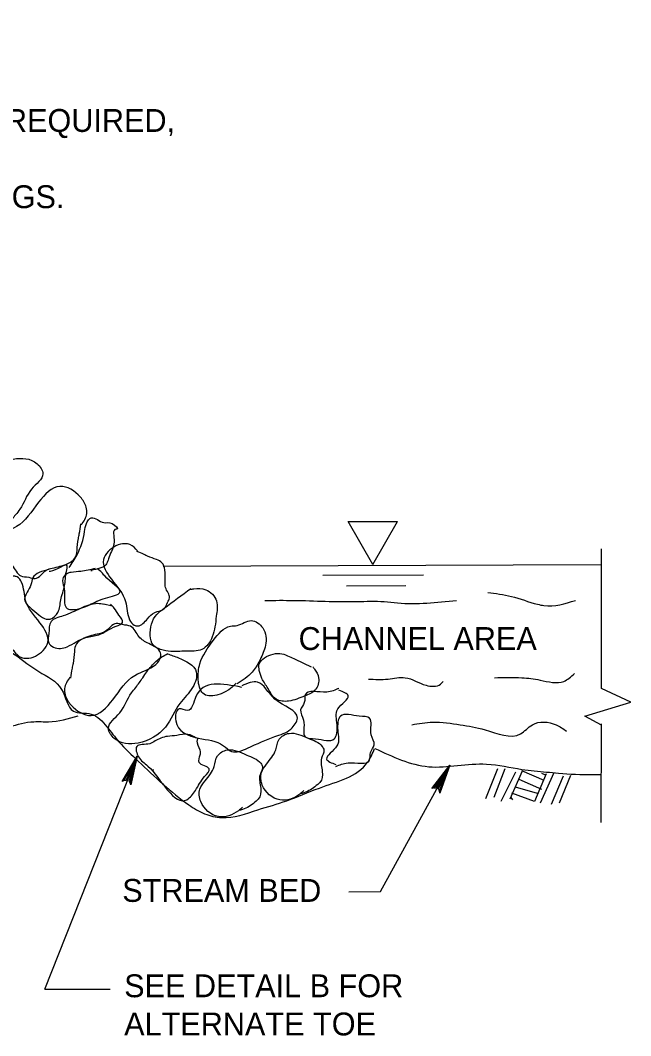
# Model space of a CAD drawing. Extents: x 5 to 910, y -47 to 547.
# Drawn here: x 524.8 to 598, y 110.4 to 232.2 of the extents above; entities that cross this region are included whole.
import ezdxf

# ---------------------------------------------------------------- set-up
doc = ezdxf.new("R2010")
doc.units = 0
for name, color, linetype in [('1', 7, 'Continuous'), ('2', 7, 'Continuous'), ('3', 7, 'Continuous')]:
    doc.layers.add(name, color=color, linetype=linetype)

msp = doc.modelspace()

# ---------------------------------------------------------------- linework, layer by layer
at = {"layer": '1'}
for p, q in [((582, 142.38), (580.54, 138.76)), ((582.85, 142.36), (581.55, 138.92)), ((584.13, 141.99), (582.39, 138.44)), ((584.93, 142.1), (583.47, 138.72)), ((587.59, 140.96), (584.89, 142.13)), ((587.81, 141.76), (586.44, 138.47)), ((588.73, 141.88), (587.1, 138.26)), ((587.77, 141.62), (587.31, 141.81)), ((589.87, 141.51), (588.41, 138.08)), ((590.74, 141.58), (589.39, 138.24)), ((586.78, 139.4), (584.13, 140.16)), ((587.29, 139.88), (584.59, 141.1)), ((583.81, 138.65), (583.63, 138.95)), ((586.44, 138.47), (583.72, 139.47))]:
    msp.add_line(p, q, dxfattribs=at)
at = {"layer": '2'}
for p, q in [((564.09, 172.03), (570.01, 172.03)), ((567.04, 166.88), (564.09, 172.03)), ((567.04, 166.88), (570.01, 172.03)), ((594.47, 152.03), (594.47, 168.76)), ((541.92, 166.7), (594.38, 166.9)), ((561.05, 165.6), (573.13, 165.65)), ((563.88, 164.32), (570.98, 164.37)), ((594.43, 135.93), (594.45, 147.76)), ((527.73, 115.95), (538.81, 143.91)), ((567.98, 127.67), (576.28, 142.81)), ((564.18, 127.62), (567.98, 127.67)), ((527.73, 115.95), (535.54, 115.95))]:
    msp.add_line(p, q, dxfattribs=at)
for points in [[(594.47, 147.62), (592.46, 148.69), (597.95, 150.39), (594.47, 152.03)], [(537.21, 140.98), (537.46, 141.01), (538.81, 143.91), (537.21, 140.98), (537, 140.87), (538.81, 143.91), (537.78, 140.89), (537.96, 140.69), (538.81, 143.91), (538.03, 140.46), (537.96, 140.69)], [(574.32, 140.09), (574.59, 140.09), (576.28, 142.81), (574.32, 140.09), (574.11, 140.02), (576.28, 142.81), (574.89, 139.93), (575.05, 139.72), (576.28, 142.81), (575.09, 139.47), (575.05, 139.72)]]:
    msp.add_lwpolyline(points, dxfattribs=at)
for points in [[(580.81, 163.54), (583.65, 163.06), (586.78, 162.12), (587.56, 161.96), (591.34, 162.58)], [(554.11, 162.58), (557.57, 162.58), (565.12, 162.44), (568.41, 162.44), (569.99, 162.28), (577.06, 162.58)], [(581.61, 153.31), (584.91, 153.31), (587.1, 153.02), (589.94, 152.86), (591.2, 153.8)], [(566.51, 153.15), (568.87, 153.15), (570.93, 153.31), (573.42, 152.4), (575.16, 152.54), (575.48, 152.86)], [(503.41, 144.9), (508.88, 143.93), (512.06, 145.01), (517.53, 145.88), (520.55, 146.43), (526.41, 148.03), (528.17, 148.03), (531.72, 148.72)], [(571.71, 147.66), (574.22, 147.98), (577.52, 147.66), (580.49, 147.05), (584.75, 146.57), (586.17, 147.66), (589, 147.66), (590.26, 146.89)], [(567.29, 144.83), (573.74, 142.63), (580.68, 142.95), (584.91, 142.31), (587.88, 141.99), (589.3, 141.85), (593.37, 141.69), (594.33, 141.69)]]:
    msp.add_spline(points, degree=3, dxfattribs=at)
at = {"layer": '3'}
for p, q in [((534.78, 162.17), (535.79, 161.92)), ((557.75, 155.53), (559.63, 154.6)), ((540.71, 142.29), (540.68, 142.08))]:
    msp.add_line(p, q, dxfattribs=at)
for points in [[(455.6, 232.18), (447.66, 230.07), (438.55, 227.81), (435.12, 226.62), (434.05, 223.3), (435.12, 222.13), (440.2, 217.4), (445.42, 213.35), (450.86, 208.86), (456.67, 204.95), (462.35, 201.15), (469.35, 196.3), (476.67, 190.15), (481.77, 185.67), (486.39, 181.98), (489.82, 180.11), (491.36, 179.49), (493.97, 176.19), (495.86, 174.75), (498.93, 174.39), (499.05, 172.99), (499.64, 172.62), (500.72, 172.62), (502.61, 170.86), (505.93, 168.37), (508.88, 166.01), (509.25, 165.05), (510.9, 164.57), (514.1, 162.33), (516.23, 160.54), (520.48, 158.19), (524.17, 156.04), (527, 154.05), (529.73, 151.9), (531.14, 149.31), (533.27, 148.94), (535.17, 147.41), (536.59, 145.63), (538.95, 143.27), (544.99, 138.05), (546.88, 136.98), (548.9, 136.52), (553.27, 137.46), (556.72, 138.54), (560.63, 140.07), (566.42, 143.16), (567.25, 144.8)], [(520.44, 168.83), (519.09, 169.33), (516.96, 171), (517.39, 172.88), (518.95, 174.8), (520.67, 177.63), (523.94, 179.53), (526.8, 178.98), (527.48, 177.77), (526.13, 175.94), (524.74, 173.52), (524.21, 172.85), (523.39, 171.71), (522.36, 170.29), (521.12, 169.24), (520.39, 168.83)], [(532.1, 171.66), (532.75, 172.99), (532.68, 173.77), (531.99, 174.98), (529.54, 176.26), (526.98, 174.36), (524.33, 171.43), (521.81, 170.13), (521.24, 169.26), (521.26, 168.73), (522.68, 167.61), (523.82, 166.77), (524.83, 165.53), (525.79, 165.35), (526.55, 165.21), (527.89, 166.2), (528.6, 166.45), (530.46, 167), (531.33, 167.66), (531.58, 168.57), (531.74, 169.99), (531.85, 170.57), (532.04, 171.75)], [(530.64, 166.52), (531.58, 168.03), (532.49, 170.86), (532.7, 171.8), (533.29, 172.49), (534.78, 171.91), (535.81, 171.8), (536.38, 171.11), (536.27, 171.11), (536.04, 169.63), (535.7, 168.46), (535.35, 167.57), (534.55, 166.52), (533.29, 166.17), (533.41, 166.17)], [(538.85, 168.51), (537.92, 169.28), (537.32, 169.38), (536.25, 169.12), (534.76, 167.48), (535.7, 165.12), (537.41, 162.44), (537.89, 160.25), (538.44, 159.61), (538.85, 159.51), (540.02, 160.38), (540.89, 161.12), (542.08, 161.64), (542.42, 162.33), (542.67, 162.88), (542.19, 164.14), (542.15, 164.73), (542.1, 166.26), (541.76, 167.09), (541.12, 167.48), (540.04, 167.87), (539.61, 168.09), (538.76, 168.46)], [(528.24, 166.29), (526.29, 165.28), (526.06, 164.46), (525.29, 162.74), (526.52, 161.25), (528.35, 160.34), (529.29, 161.14), (529.63, 162.63), (530.09, 164.34), (530.3, 166.06), (530.41, 166.74), (528.35, 166.06), (528.24, 166.06)], [(533.75, 166.4), (532.04, 166.06), (530.89, 165.94), (530.3, 165.74), (529.86, 165.17), (529.98, 164.23), (530.09, 163.2), (530.41, 161.6), (531.12, 161.48), (533.07, 162.05), (535.01, 162.86), (536.73, 163.54), (534.9, 165.51), (534.55, 165.94), (533.98, 166.4)], [(524.01, 156.49), (524.92, 155.72), (525.52, 155.63), (526.59, 155.9), (528.08, 157.52), (527.14, 159.9), (525.42, 162.56), (524.94, 164.75), (524.39, 165.39), (524.01, 165.49), (522.84, 164.64), (521.95, 163.91), (520.78, 163.38), (520.44, 162.69), (520.16, 162.15), (520.64, 160.89), (520.69, 160.29), (520.73, 158.74), (521.08, 157.91), (521.72, 157.52), (522.79, 157.16), (523.23, 156.93), (524.1, 156.54)], [(545.15, 163.91), (545.58, 163.98), (547.02, 163.86), (548.3, 162.51), (548.28, 160.68), (547.8, 158.21), (546.56, 156.7), (544.6, 156.49), (542.83, 156.45), (541.6, 156.7), (540.73, 157.2), (540.36, 158.35), (541.14, 160.89), (542.03, 161.64), (545.24, 164.02)], [(534.85, 162.1), (534.05, 162.19), (531.99, 161.62), (529.93, 160.73), (528.47, 160.04), (528.19, 158.62), (528.19, 157.48), (529.59, 156.82), (530.39, 157.02), (532.63, 158.12), (534.19, 158.46), (536.27, 159.49), (537.05, 159.93), (536.61, 160.8), (536.04, 161.64), (535.61, 162.12)], [(530.73, 153.36), (530.09, 152.01), (530.16, 151.26), (530.85, 150.04), (533.29, 148.76), (535.86, 150.66), (538.51, 153.59), (541.03, 154.89), (541.6, 155.76), (541.6, 156.27), (540.18, 157.39), (539.01, 158.23), (538.01, 159.47), (537.05, 159.67), (536.29, 159.81), (534.94, 158.83), (534.23, 158.58), (532.38, 158.03), (531.51, 157.36), (531.26, 156.43), (531.1, 155.03), (530.98, 154.44), (530.8, 153.27)], [(550.64, 152.67), (550.16, 152.17), (546.66, 151.44), (546.11, 153.06), (546.31, 154.98), (547.94, 157.8), (549.97, 159.49), (550.77, 159.58), (552.47, 160.16), (553.84, 159.29), (554.18, 157.2), (553.52, 155.47), (553.45, 155.33), (552.58, 153.98), (550.77, 152.58)], [(542.42, 156.17), (543.75, 155.69), (545.88, 154), (545.44, 152.15), (543.91, 150.23), (542.19, 147.39), (538.9, 145.47), (536.04, 146.02), (535.35, 147.23), (536.7, 149.08), (538.1, 151.48), (538.63, 152.15), (539.45, 153.31), (540.5, 154.71), (541.74, 155.79), (542.45, 156.2)], [(559.83, 154.62), (560.06, 154.34), (560.54, 153.29), (560.15, 151.85), (558.87, 151.12), (556.95, 150.5), (555.44, 150.73), (554.48, 152.01), (553.75, 153.22), (553.43, 154.18), (553.43, 154.96), (554.07, 155.69), (556.15, 156.17), (557.02, 155.85), (557.75, 155.53)], [(551.32, 152.15), (545.83, 151.07), (544.83, 149.36), (543.82, 149.56), (543.41, 148.14), (546.11, 146.06), (549.13, 145.15), (550.11, 144.46), (552.01, 144.85), (555.3, 146.25), (557.2, 147.14), (558, 148.46), (555.3, 150.75), (553.22, 152.77), (551.32, 152.35)], [(562.97, 152.03), (561.53, 151.58), (558.94, 151.26), (558.83, 150.34), (558.39, 149.45), (558.74, 148.21), (558.94, 146.2), (560.18, 145.97), (562.42, 145.97), (562.76, 147.66), (562.85, 149.56), (564.09, 151.14), (562.97, 151.8)], [(562.62, 142.65), (564.07, 143.09), (566.65, 143.43), (566.77, 144.35), (567.2, 145.24), (566.86, 146.45), (566.65, 148.46), (565.42, 148.69), (563.17, 148.69), (562.83, 147.02), (562.74, 145.12), (561.5, 143.55), (562.62, 142.88)], [(545.88, 146.06), (544.87, 146.5), (543.54, 146.38), (542.42, 146.27), (541.62, 146.06), (540.96, 145.72), (540.3, 145.38), (538.74, 145.06), (538.95, 143.82), (540.07, 142.7), (544.76, 138.67), (545.79, 139.79), (546.88, 141.46), (547.43, 142.36), (546.22, 143.13), (546.34, 144.05), (546.34, 144.6), (545.99, 145.72), (546.11, 146.06)], [(558.78, 139.77), (558.3, 139.34), (555.9, 138.65), (553.79, 140.43), (553.7, 141.94), (554.3, 142.95), (555.4, 144.64), (555.81, 145.92), (557, 146.63), (559.28, 146.04), (560.98, 145.06), (561.18, 144.64), (560.89, 143.64), (560.98, 142.04), (560.7, 140.75), (560.59, 140.64), (559.19, 139.66), (558.37, 139.36)], [(551.41, 137.76), (550.93, 137.35), (548.53, 136.64), (546.43, 138.44), (546.31, 139.95), (546.93, 140.94), (548.03, 142.65), (548.42, 143.93), (549.61, 144.64), (551.92, 144.03), (553.61, 143.04), (553.82, 142.65), (553.52, 141.65), (553.61, 140.05), (553.31, 138.74), (553.22, 138.65), (551.83, 137.64), (550.98, 137.37)]]:
    msp.add_spline(points, degree=3, dxfattribs=at)

# ---------------------------------------------------------------- texts
for s, height, p in [('THICKNESS, AS REQUIRED,', 2.7454, (493.97, 218.79)), ('ON THE DRAWINGS.', 2.7454, (493.97, 209.64)), ('CHANNEL AREA', 2.7454, (558.14, 156.63)), ('STREAM BED', 2.745, (537, 126.41)), ('SEE DETAIL B FOR', 2.7454, (537.23, 114.97)), ('ALTERNATE TOE', 2.7454, (537.23, 110.39))]:
    msp.add_text(s, height=height, dxfattribs=at).set_placement(p)

doc.saveas('drawing.dxf')
